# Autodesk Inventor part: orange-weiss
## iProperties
Created: 2004-10
Part Number: orange-weiss
Document SubType Name: Modeling
Designer: sahrens
Manufacturer: Standard
Standards Organization: Custom
Author: sahrens
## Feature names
1. Extrusion1
2. Rundung2 [Fillet]
